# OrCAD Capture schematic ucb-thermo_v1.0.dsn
size C; title: UCB_Thermo-Interface; rev: 1.0; company: University of Arkansas (NCREPT); note: 700 W. Research Center Blvd.; note: Fayetteville, AR 72701
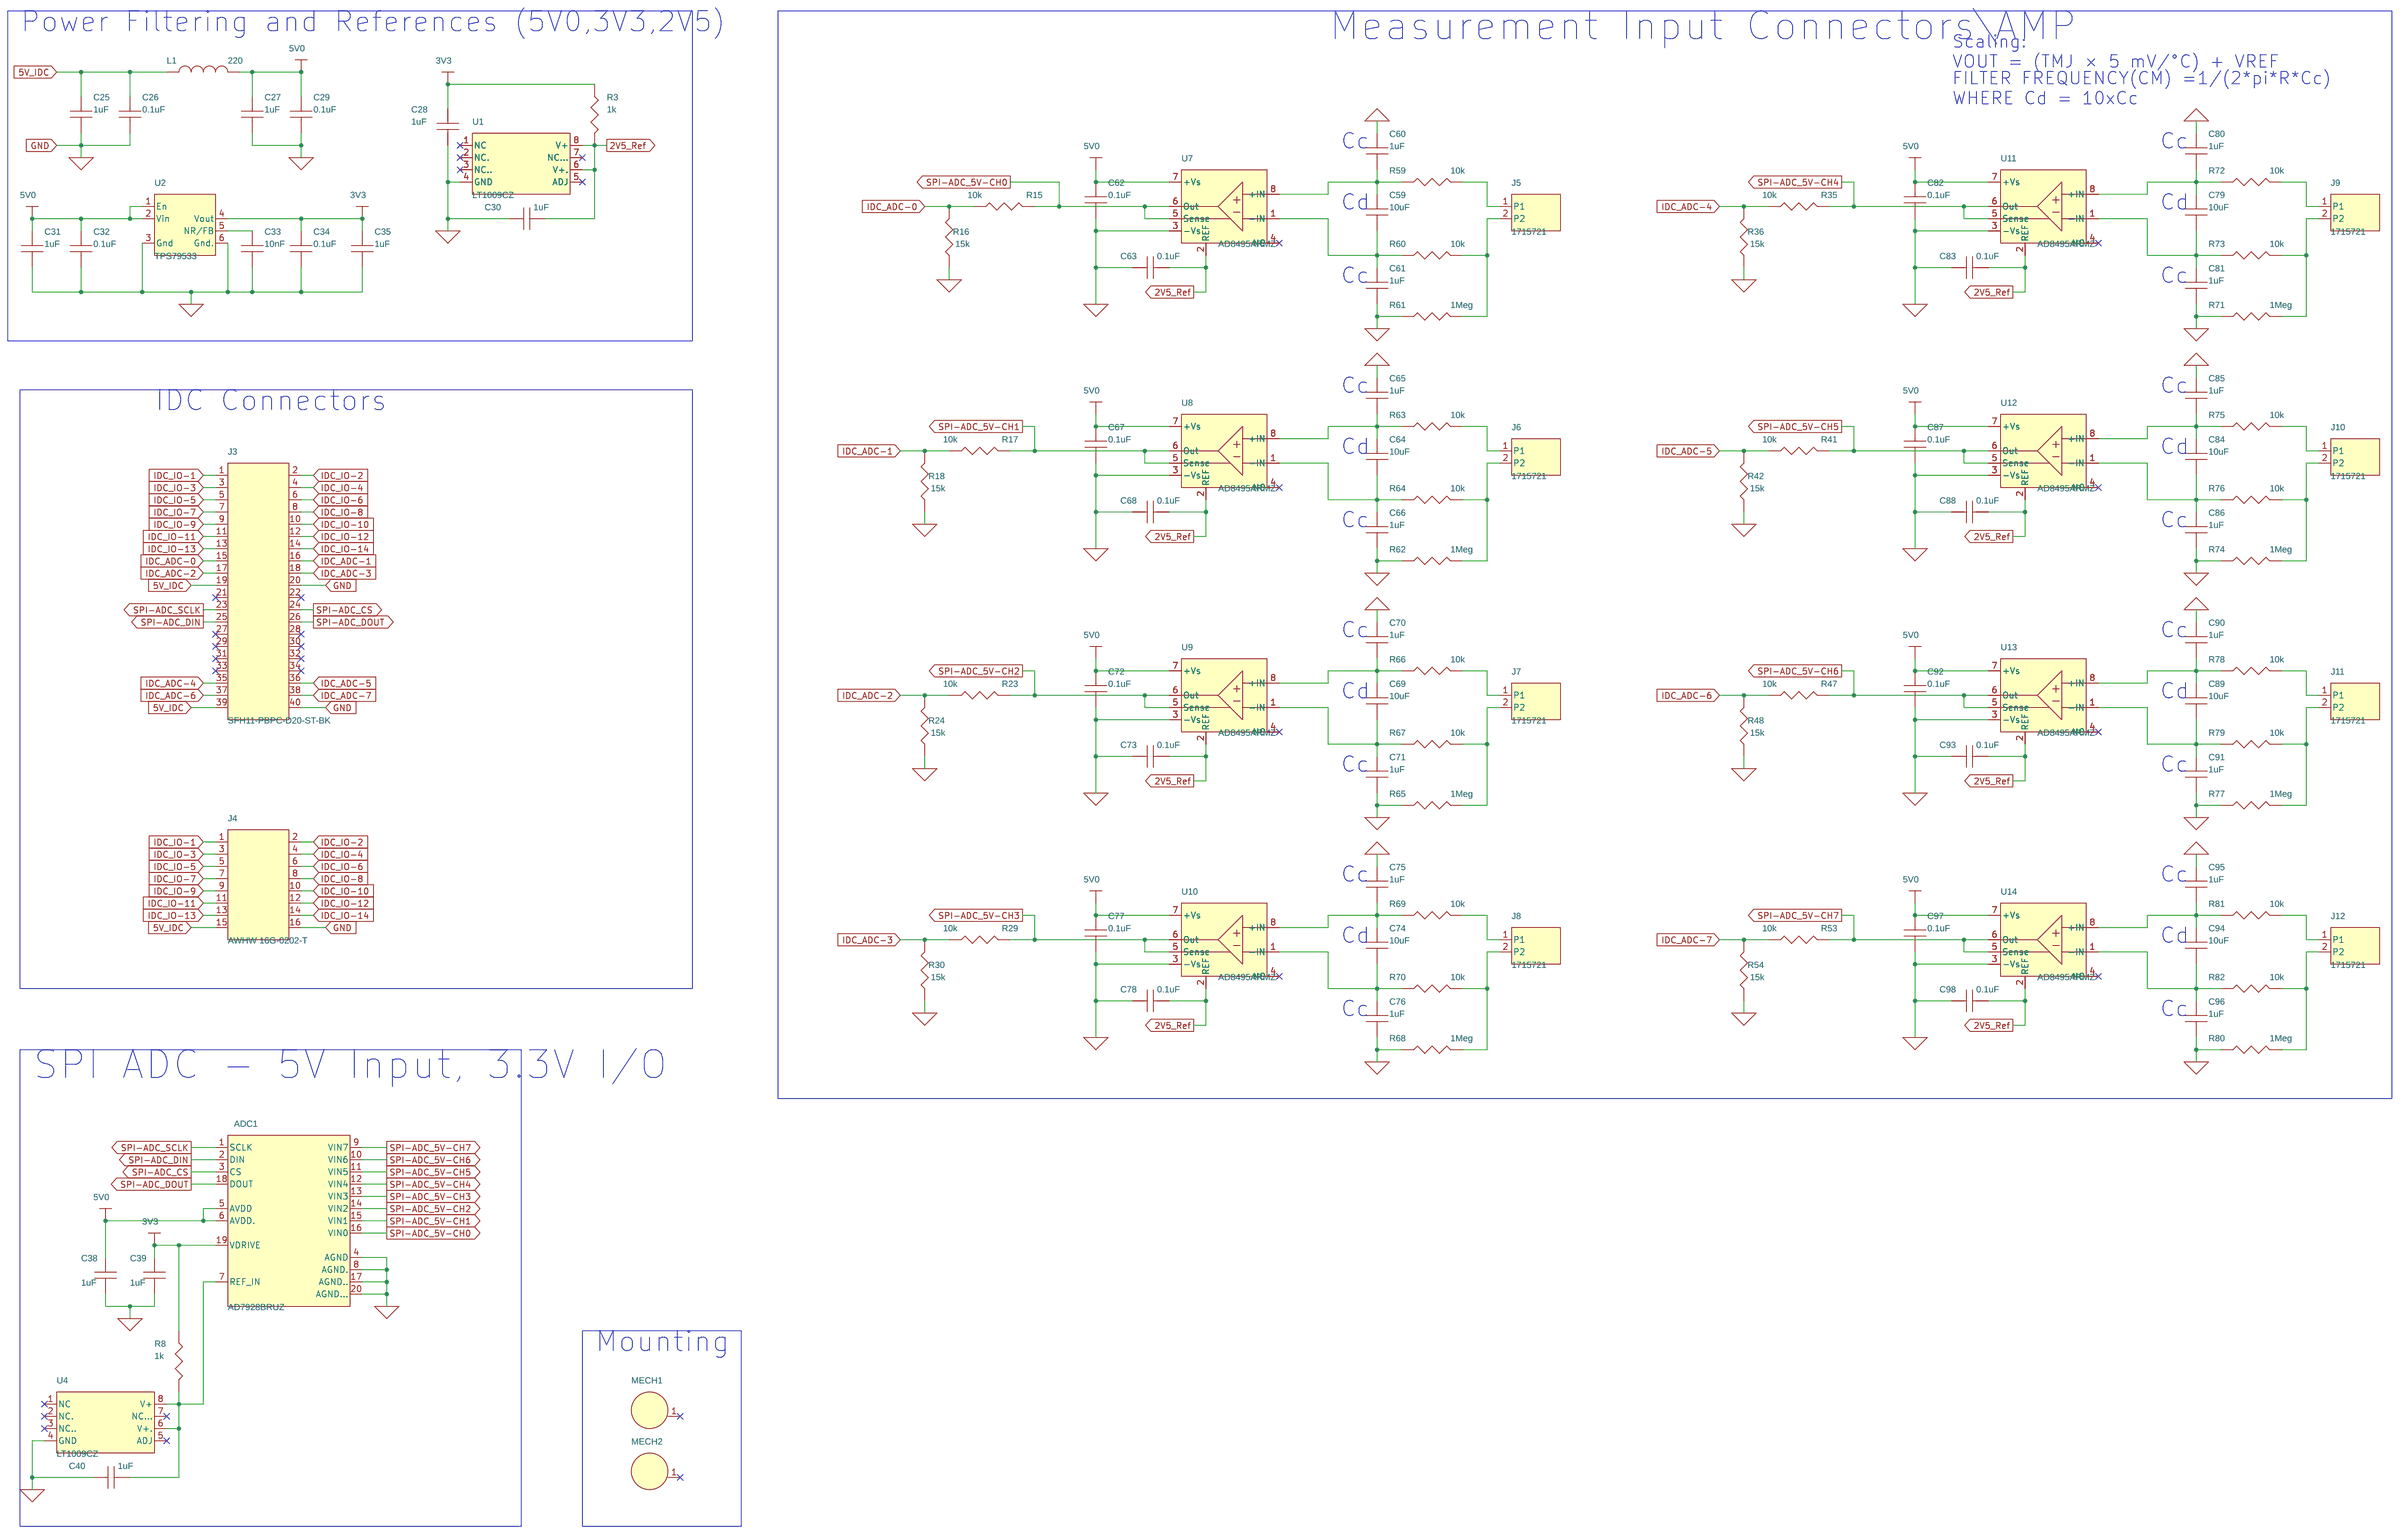
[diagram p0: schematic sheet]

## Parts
ADC1  AD7928BRUZ  [20-TSSOP]
C25  1uF  [C_0603]
C26  0.1uF  [C_0603]
C27  1uF  [C_0603]
C28  1uF  [C_0603]
C29  0.1uF  [C_0603]
C30  1uF  [C_0603]
C31  1uF  [C_0603]
C32  0.1uF  [C_0603]
C33  10nF  [C_0603]
C34  0.1uF  [C_0603]
C35  1uF  [C_0603]
C38  1uF  [C_0603]
C39  1uF  [C_0603]
C40  1uF  [C_0603]
C59  10uF  [C_1206]
C60  1uF  [C_0603]
C61  1uF  [C_0603]
C62  0.1uF  [C_0603]
C63  0.1uF  [C_0603]
C64  10uF  [C_1206]
C65  1uF  [C_0603]
C66  1uF  [C_0603]
C67  0.1uF  [C_0603]
C68  0.1uF  [C_0603]
C69  10uF  [C_1206]
C70  1uF  [C_0603]
C71  1uF  [C_0603]
C72  0.1uF  [C_0603]
C73  0.1uF  [C_0603]
C74  10uF  [C_1206]
C75  1uF  [C_0603]
C76  1uF  [C_0603]
C77  0.1uF  [C_0603]
C78  0.1uF  [C_0603]
C79  10uF  [C_1206]
C80  1uF  [C_0603]
C81  1uF  [C_0603]
C82  0.1uF  [C_0603]
C83  0.1uF  [C_0603]
C84  10uF  [C_1206]
C85  1uF  [C_0603]
C86  1uF  [C_0603]
C87  0.1uF  [C_0603]
C88  0.1uF  [C_0603]
C89  10uF  [C_1206]
C90  1uF  [C_0603]
C91  1uF  [C_0603]
C92  0.1uF  [C_0603]
C93  0.1uF  [C_0603]
C94  10uF  [C_1206]
C95  1uF  [C_0603]
C96  1uF  [C_0603]
C97  0.1uF  [C_0603]
C98  0.1uF  [C_0603]
J3  SFH11-PBPC-D20-ST-BK  [40-IDC-F_MNT]
J4  AWHW 16G-0202-T  [16-IDC-M]
J5  1715721  [1715721]
J6  1715721  [1715721]
J7  1715721  [1715721]
J8  1715721  [1715721]
J9  1715721  [1715721]
J10  1715721  [1715721]
J11  1715721  [1715721]
J12  1715721  [1715721]
L1  220  [L_0805]
MECH1  Mech_Hole  [4-40_SCREW]
MECH2  Mech_Hole  [4-40_SCREW]
R3  1k  [R_0805]
R8  1k  [R_0805]
R15  10k  [R_0603]
R16  15k  [R_0603]
R17  10k  [R_0603]
R18  15k  [R_0603]
R23  10k  [R_0603]
R24  15k  [R_0603]
R29  10k  [R_0603]
R30  15k  [R_0603]
R35  10k  [R_0603]
R36  15k  [R_0603]
R41  10k  [R_0603]
R42  15k  [R_0603]
R47  10k  [R_0603]
R48  15k  [R_0603]
R53  10k  [R_0603]
R54  15k  [R_0603]
R59  10k  [R_0603]
R60  10k  [R_0603]
R61  1Meg  [R_0603]
R62  1Meg  [R_0603]
R63  10k  [R_0603]
R64  10k  [R_0603]
R65  1Meg  [R_0603]
R66  10k  [R_0603]
R67  10k  [R_0603]
R68  1Meg  [R_0603]
R69  10k  [R_0603]
R70  10k  [R_0603]
R71  1Meg  [R_0603]
R72  10k  [R_0603]
R73  10k  [R_0603]
R74  1Meg  [R_0603]
R75  10k  [R_0603]
R76  10k  [R_0603]
R77  1Meg  [R_0603]
R78  10k  [R_0603]
R79  10k  [R_0603]
R80  1Meg  [R_0603]
R81  10k  [R_0603]
R82  10k  [R_0603]
U1  LT1009CZ  [8-MSOP]
U2  TPS79533  [SOT-223-6]
U4  LT1009CZ  [8-MSOP]
U7  AD8495ARMZ  [8-MSOP]
U8  AD8495ARMZ  [8-MSOP]
U9  AD8495ARMZ  [8-MSOP]
U10  AD8495ARMZ  [8-MSOP]
U11  AD8495ARMZ  [8-MSOP]
U12  AD8495ARMZ  [8-MSOP]
U13  AD8495ARMZ  [8-MSOP]
U14  AD8495ARMZ  [8-MSOP]

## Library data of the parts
ADC1 = AD7928BRUZ: ADC 8-Ch, 12-Bit, 1MSPS; Manufacturer: Analog Devices; Part_Number: IC-00023; STEP_Model: TSSOP65P640X120-20N.stp; Datasheet: AnalogDevices-AD7908_7918_7928-877555.pdf
C25 C27 C28 C30 C31 C35 C38-C40 C60 C61 C65 C66 C70 C71 C75 C76 C80 C81 C85 C86 C90 C91 C95 C96 = CAP_NP: 1µF ±10% 35V X7R MLCC; Manufacturer: TDK; Manufacturer_Part_Number: C1608X7R1V105K080AC; Part_Number: Cap-00008; Tolerance: 10%; Voltage: 35V; Datasheet: TDK-mlcc_commercial_general_en.pdf
C26 C29 C32 C34 C62 C63 C67 C68 C72 C73 C77 C78 C82 C83 C87 C88 C92 C93 C97 C98 = CAP_NP: 0.1µF ±10% 50V X7R MLCC; Manufacturer: TDK; Manufacturer_Part_Number: C1608X7R1H104K080AA; Part_Number: Cap-00001; Tolerance: 10%; Voltage: 50V; Datasheet: TDK-mlcc_commercial_general_en.pdf
C33 = CAP_NP: 10nF ±10% 100V X7R MLCC; Manufacturer: TDK; Manufacturer_Part_Number: C1608X7R2A103K080AA; Part_Number: TMP-222; Tolerance: 10%; Voltage: 100V; Datasheet: TDK-mlcc_commercial_general_en.pdf
C59 C64 C69 C74 C79 C84 C89 C94 = CAP_NP: 10µF ±20% 35V X7R MLCC; Manufacturer: TDK; Manufacturer_Part_Number: C3216X7R1V106M160AC; Part_Number: Cap-00002; Tolerance: 20%; Voltage: 35V; Datasheet: TDK-mlcc_commercial_general_en.pdf
J3 = Header_2x20: 40-POS Header, Shrouded, 0.100", TH, Female w/ Mounting; Manufacturer: Sullins; Part_Number: Con-00020; STEP_Model: SFH11-P_ _C-D20-ST-_ _.stp; Datasheet: Sullins-146_PAGE119_.100_SFH11_SERIES_FEMALE_HDR_ST_RA.pdf
J4 = Header_2x8: 16-POS Header, Shrouded, 0.100", TH; Manufacturer: Assmann; Part_Number: Con-00014; STEP_Model: HDB-16.stp; User_Field1: SBH11-PBPC-D08-ST-BK; Datasheet: SBH11-PBPC-D08-ST-BK
J5-J12 = Connector-2: PCB Terminal Block, 2-position, 90 degrees, 5.08mm; Manufacturer: Phoenix Contact; Part_Number: Con-00006; Rating: 17.5A; STEP_Model: 1715721.stp; Voltage: 400V; Datasheet: PhoenixContact-1715734.pdf
L1 = Ind: Ferrite Bead, 220 Ohm @ 100 MHz, 2A; Manufacturer: Murata; Manufacturer_Part_Number: BLM21PG221SN1D; Part_Number: Ind-00001; Rating: 2A; Tolerance: 25%; Datasheet: Murata-L0110S0100BLM21P.pdf
MECH1 MECH2 = Mech_Hole: Mounting Hole for 4-40 Screw, 0.125"; Part_Number: Con-00005
R3 R8 = R-Standard: 1k Ohm, 1%, 0805; Manufacturer: KOA Speer; Manufacturer_Part_Number: RK73H2ATTD1001F; Part_Number: Res-00012; Rating: 0.125W; Tolerance: 1%; Datasheet: KOA-RK73H-5715.pdf
R15 R17 R23 R29 R35 R41 R47 R53 R59 R60 R63 R64 R66 R67 R69 R70 R72 R73 R75 R76 R78 R79 R81 R82 = R-Standard: 10k Ohm, 1%, 0603; Manufacturer: KOA Speer; Manufacturer_Part_Number: RK73H1JTTD1002F; Part_Number: Res-00031; Rating: 0.1W; Tolerance: 1%; Datasheet: KOA-RK73H-5715.pdf
R16 R18 R24 R30 R36 R42 R48 R54 = R-Standard: 15k Ohm, 1%, 0603; Manufacturer: KOA Speer; Manufacturer_Part_Number: RK73H1JTTD1502F; Part_Number: Res-00037; Rating: 0.1W; Tolerance: 1%; Datasheet: KOA-RK73H-5715.pdf
R61 R62 R65 R68 R71 R74 R77 R80 = R-Standard: 1M Ohm, 1%, 0603; Manufacturer: KOA Speer; Manufacturer_Part_Number: RK73H1JTTD1004F; Part_Number: Res-00035; Rating: 0.1W; Tolerance: 1%; Datasheet: KOA-RK73H-5715.pdf
U1 U4 = LT1009CZ: 2.5V Voltage Reference, ±0.2%, SMD; Manufacturer: Linear Tech; Manufacturer_Part_Number: LT1009CMS8#PBF; Part_Number: IC-00024; STEP_Model: MSOP8.stp; Datasheet: LinearTech-1009ff.pdf
U2 = TPS795: LDO Voltage Reg, 3.3V, 500mA, 2%; Manufacturer: TI; Manufacturer_Part_Number: TPS79533DCQR; Part_Number: IC-00025; STEP_Model: SOT-223-6.stp; Datasheet: TI-tps795-706600.pdf
U7-U14 = AD849X: K-Type Thermocouple Amplifier w/ Cold Jct Comp; Manufacturer: Analog Devices; Manufacturer_Part_Number: AD8495ARMZ-ND; Part_Number: TMP-233; Datasheet: AnalogDevices_AD8495.pdf

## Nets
2V5_Ref: C30.2 C63.2 C68.2 C73.2 C78.2 C83.2 C88.2 C93.2 C98.2 R3.2 U1.6(V+.) U1.8(V+) U7.2(REF) U8.2(REF) U9.2(REF) U10.2(REF) U11.2(REF) U12.2(REF) U13.2(REF) U14.2(REF)
3V3: ADC1.19(VDRIVE) C28.1 C34.1 C35.1 C39.1 R3.1 R8.1 U2.4(Vout)
5V0: ADC1.5(AVDD) ADC1.6(AVDD.) C27.1 C29.1 C31.1 C32.1 C38.1 C62.1 C67.1 C72.1 C77.1 C82.1 C87.1 C92.1 C97.1 L1.2 U2.1(En) U2.2(Vin) U7.7(+Vs) U8.7(+Vs) U9.7(+Vs) U10.7(+Vs) U11.7(+Vs) U12.7(+Vs) U13.7(+Vs) U14.7(+Vs)
5V_IDC: C25.1 C26.1 J3.19 J3.39 J4.15 L1.1
GND_SIGNAL: ADC1.4(AGND) ADC1.8(AGND.) ADC1.17(AGND..) ADC1.20(AGND...) C25.2 C26.2 C27.2 C28.2 C29.2 C30.1 C31.2 C32.2 C33.2 C34.2 C35.2 C38.2 C39.2 C40.1 C60.1 C61.2 C62.2 C63.1 C65.1 C66.2 C67.2 C68.1 C70.1 C71.2 C72.2 C73.1 C75.1 C76.2 C77.2 C78.1 C80.1 C81.2 C82.2 C83.1 C85.1 C86.2 C87.2 C88.1 C90.1 C91.2 C92.2 C93.1 C95.1 C96.2 C97.2 C98.1 J3.20 J3.40 J4.16 R16.2 R18.2 R24.2 R30.2 R36.2 R42.2 R48.2 R54.2 R61.1 R62.1 R65.1 R68.1 R71.1 R74.1 R77.1 R80.1 U1.4(GND) U2.3(Gnd) U2.6(Gnd.) U4.4(GND) U7.3(-Vs) U8.3(-Vs) U9.3(-Vs) U10.3(-Vs) U11.3(-Vs) U12.3(-Vs) U13.3(-Vs) U14.3(-Vs)
IDC_ADC-0: J3.15 R15.2 R16.1
IDC_ADC-1: J3.16 R17.2 R18.1
IDC_ADC-2: J3.17 R23.2 R24.1
IDC_ADC-3: J3.18 R29.2 R30.1
IDC_ADC-4: J3.35 R35.2 R36.1
IDC_ADC-5: J3.36 R41.2 R42.1
IDC_ADC-6: J3.37 R47.2 R48.1
IDC_ADC-7: J3.38 R53.2 R54.1
IDC_IO-1: J3.1 J4.1
IDC_IO-2: J3.2 J4.2
IDC_IO-3: J3.3 J4.3
IDC_IO-4: J3.4 J4.4
IDC_IO-5: J3.5 J4.5
IDC_IO-6: J3.6 J4.6
IDC_IO-7: J3.7 J4.7
IDC_IO-8: J3.8 J4.8
IDC_IO-9: J3.9 J4.9
IDC_IO-10: J3.10 J4.10
IDC_IO-11: J3.11 J4.11
IDC_IO-12: J3.12 J4.12
IDC_IO-13: J3.13 J4.13
IDC_IO-14: J3.14 J4.14
SPI-ADC_5V-CH0: ADC1.16(VIN0) R15.1 U7.5(Sense) U7.6(Out)
SPI-ADC_5V-CH1: ADC1.15(VIN1) R17.1 U8.5(Sense) U8.6(Out)
SPI-ADC_5V-CH2: ADC1.14(VIN2) R23.1 U9.5(Sense) U9.6(Out)
SPI-ADC_5V-CH3: ADC1.13(VIN3) R29.1 U10.5(Sense) U10.6(Out)
SPI-ADC_5V-CH4: ADC1.12(VIN4) R35.1 U11.5(Sense) U11.6(Out)
SPI-ADC_5V-CH5: ADC1.11(VIN5) R41.1 U12.5(Sense) U12.6(Out)
SPI-ADC_5V-CH6: ADC1.10(VIN6) R47.1 U13.5(Sense) U13.6(Out)
SPI-ADC_5V-CH7: ADC1.9(VIN7) R53.1 U14.5(Sense) U14.6(Out)
SPI-ADC_CS: ADC1.3(CS) J3.24
SPI-ADC_DIN: ADC1.2(DIN) J3.25
SPI-ADC_DOUT: ADC1.18(DOUT) J3.26
SPI-ADC_SCLK: ADC1.1(SCLK) J3.23
N365232: ADC1.7(REF_IN) C40.2 R8.2 U4.6(V+.) U4.8(V+)
N370101: C33.1 U2.5(NR/FB)
N440352: C59.1 C60.2 R59.1 U7.8(+IN)
N440371: C59.2 C61.1 R60.1 U7.1(-IN)
N440428: J5.2(P2) R60.2 R61.2
N440435: J5.1(P1) R59.2
N443016: C64.1 C65.2 R63.1 U8.8(+IN)
N443028: C64.2 C66.1 R64.1 U8.1(-IN)
N443064: J6.2(P2) R62.2 R64.2
N443072: J6.1(P1) R63.2
N443968: C69.1 C70.2 R66.1 U9.8(+IN)
N443980: C69.2 C71.1 R67.1 U9.1(-IN)
N444016: J7.2(P2) R65.2 R67.2
N444024: J7.1(P1) R66.2
N444943: C74.1 C75.2 R69.1 U10.8(+IN)
N444955: C74.2 C76.1 R70.1 U10.1(-IN)
N444991: J8.2(P2) R68.2 R70.2
N444999: J8.1(P1) R69.2
N449385: C79.1 C80.2 R72.1 U11.8(+IN)
N449397: C79.2 C81.1 R73.1 U11.1(-IN)
N449433: J9.2(P2) R71.2 R73.2
N449441: J9.1(P1) R72.2
N449775: C84.1 C85.2 R75.1 U12.8(+IN)
N449787: C84.2 C86.1 R76.1 U12.1(-IN)
N449823: J10.2(P2) R74.2 R76.2
N449831: J10.1(P1) R75.2
N450165: C89.1 C90.2 R78.1 U13.8(+IN)
N450177: C89.2 C91.1 R79.1 U13.1(-IN)
N450213: J11.2(P2) R77.2 R79.2
N450221: J11.1(P1) R78.2
N452720: C94.1 C95.2 R81.1 U14.8(+IN)
N452732: C94.2 C96.1 R82.1 U14.1(-IN)
N452768: J12.2(P2) R80.2 R82.2
N452776: J12.1(P1) R81.2

Not connected (* = marked no-connect by the designer): J3 21* 22* 27* 28* 29* 30* 31* 32* 33* 34*; MECH1 1*; MECH2 1*; U1 1(NC)* 2(NC.)* 3(NC..)* 5(ADJ)* 7(NC...)*; U4 1(NC)* 2(NC.)* 3(NC..)* 5(ADJ)* 7(NC...)*; U7 4(NC)*; U8 4(NC)*; U9 4(NC)*; U10 4(NC)*; U11 4(NC)*; U12 4(NC)*; U13 4(NC)*; U14 4(NC)*

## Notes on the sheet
- Power Filtering and References (5V0,3V3,2V5)
- Measurement Input Connectors\AMP
- Scaling:
  VOUT = (TMJ × 5 mV/°C) + VREF
- FILTER FREQUENCY(CM) =1/(2*pi*R*Cc)
  WHERE Cd = 10xCc
- Cc
- Cc
- Cd
- Cd
- Cc
- Cc
- Cc
- Cc
- IDC Connectors
- Cd
- Cd
- Cc
- Cc
- Cc
- Cc
- Cd
- Cd
- Cc
- Cc
- Cc
- Cc
- Cd
- Cd
- Cc
- Cc
- SPI ADC - 5V Input, 3.3V I/O
- Mounting
